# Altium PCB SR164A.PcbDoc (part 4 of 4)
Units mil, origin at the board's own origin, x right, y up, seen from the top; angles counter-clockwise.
Board outline 6100 x 4100 mil, 6 copper layers (Top Layer, Signal Layer 1, Signal Layer 2, Signal Layer 3, Signal Layer 4, Bottom Layer), stack 61.4 mil thick; 254 components, 116 nets, 656 pads, 2538 vias.
Unrouted connection lines stored in the file: 13.
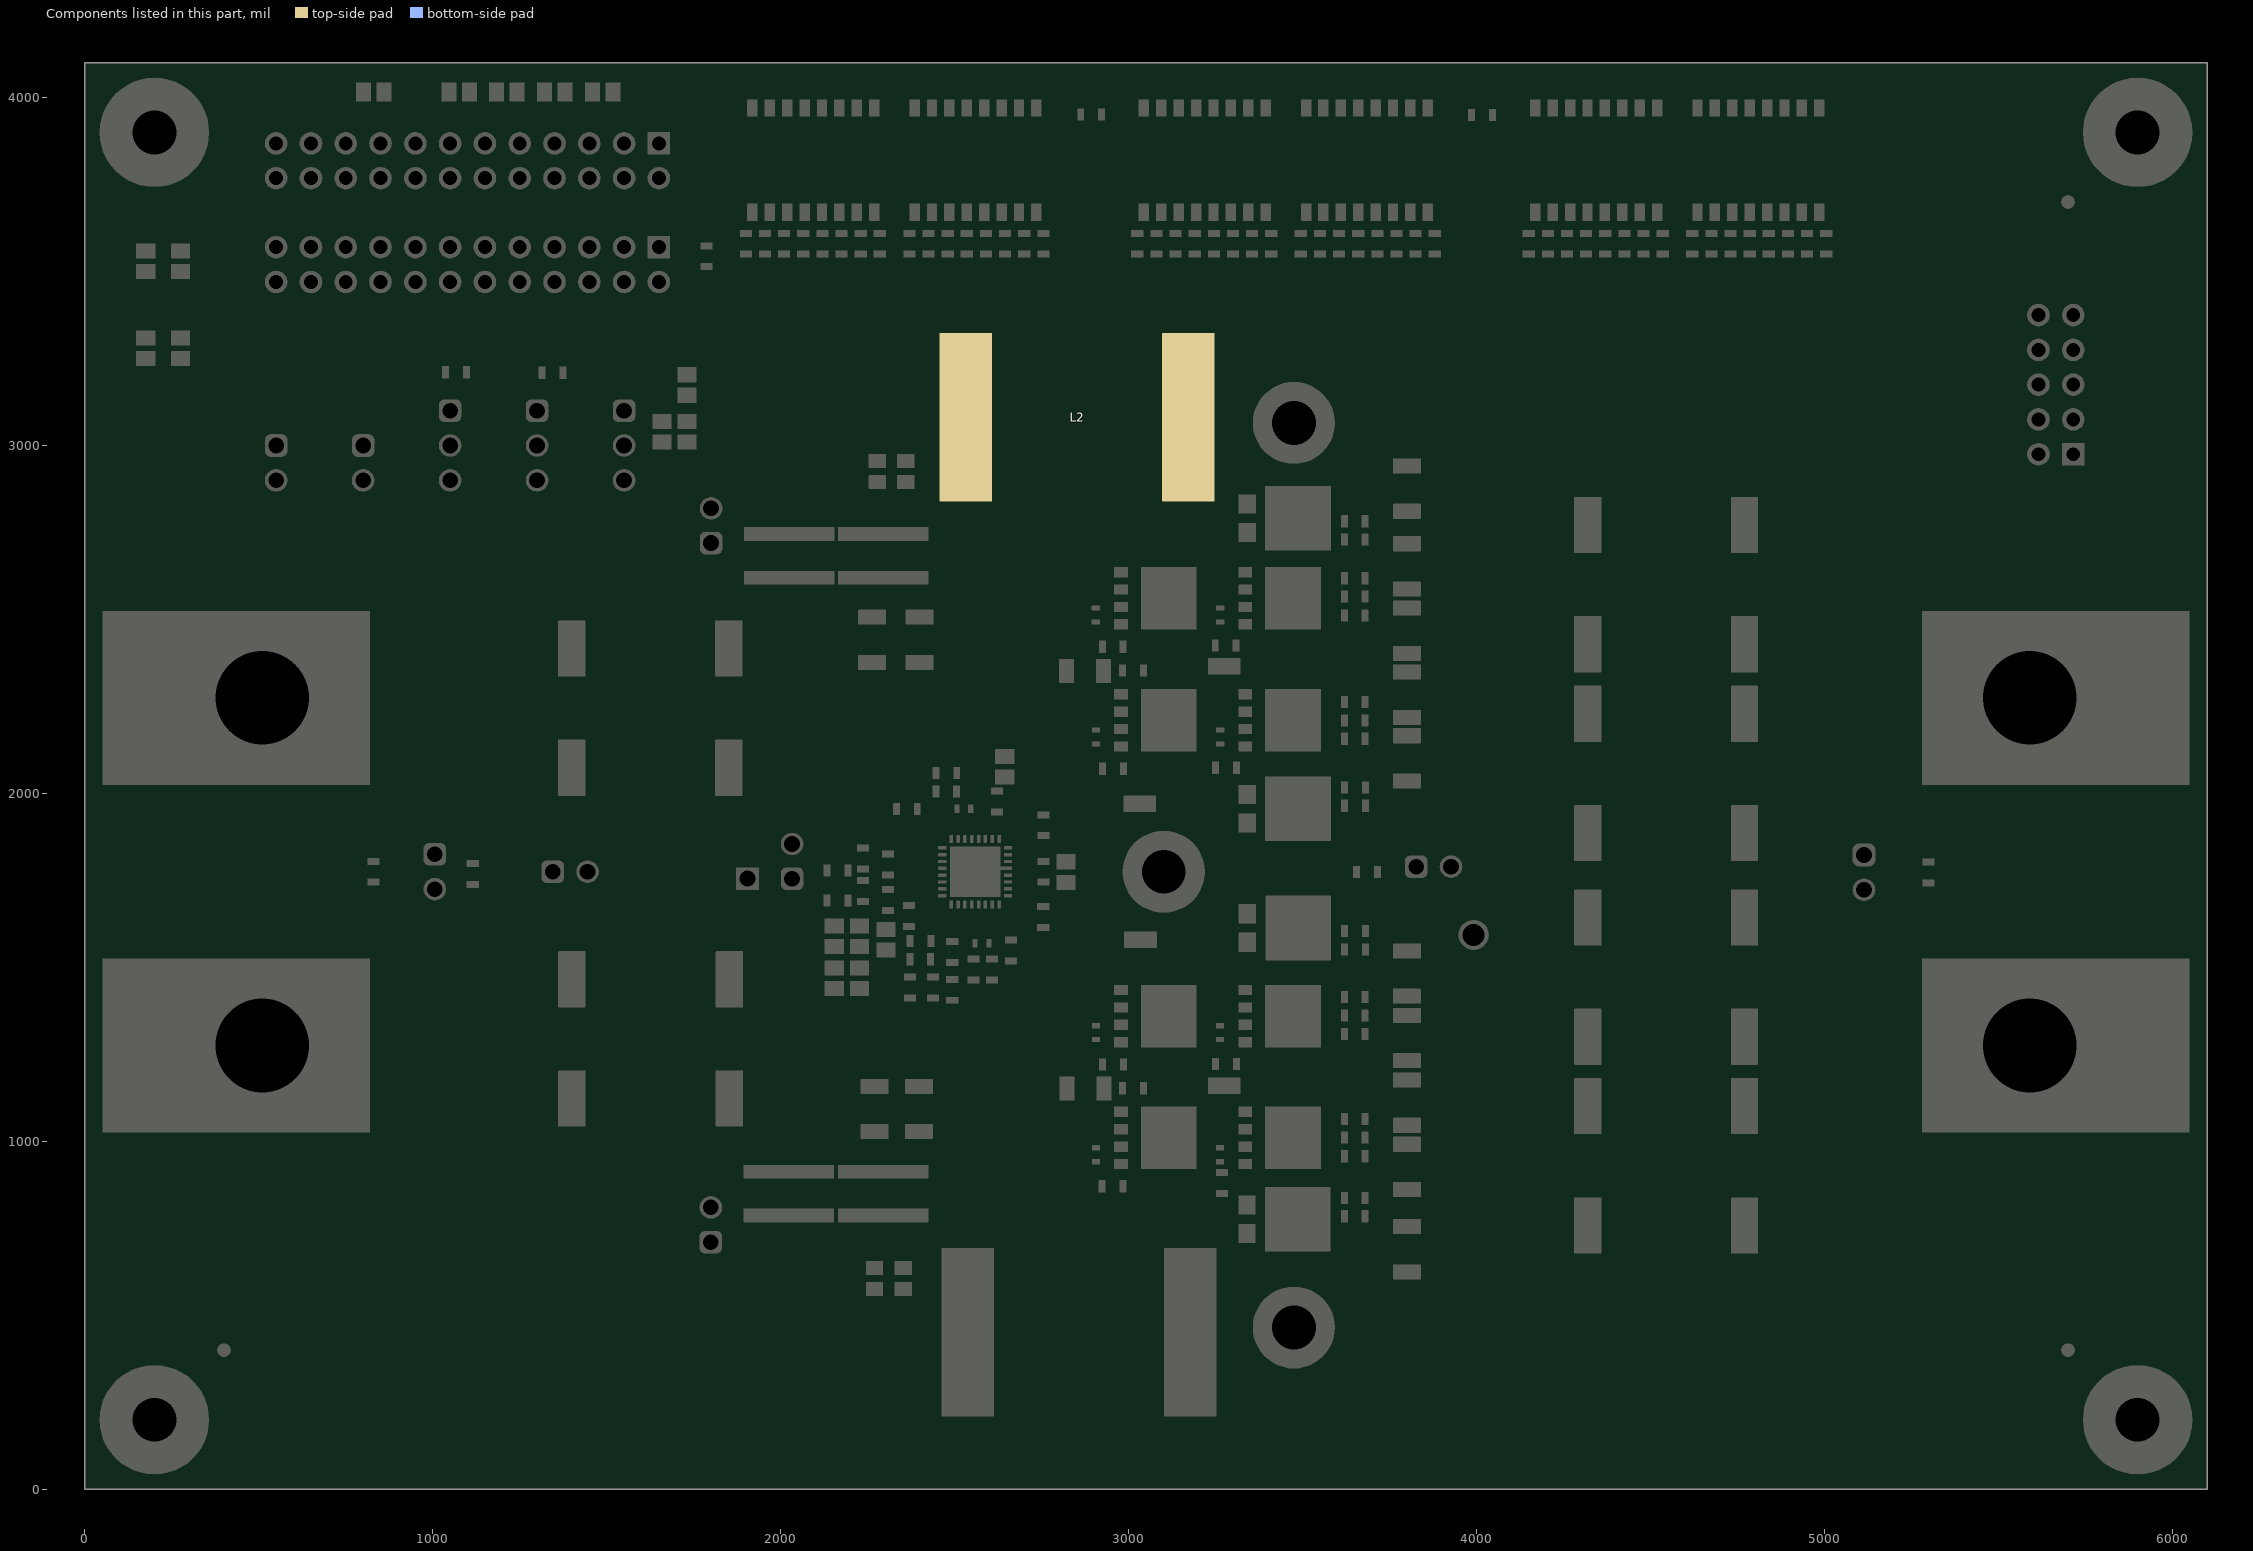
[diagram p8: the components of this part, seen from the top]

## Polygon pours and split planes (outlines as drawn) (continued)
NetC9_2 on Top Layer "TOP_LAYER_NETC9_2_P102" (solid, pour order 102): 2907.04,1185.68 2956.54,1185.68 2972.85,1169.37 2992.67,1169.37 2992.67,1134.37 2992.8,1134.24 2972.77,1134.24 2955.4,1116.87 2907.04,1116.87
NetQ4_4 on Top Layer "TOP_LAYER_NETQ4_4_P103" (solid, pour order 103): 3009.87,2066.09 3009.97,2150.41 2892.37,2150.41 2892.37,2115.7 2909.85,2098.21 2932.26,2098.21 2945.22,2085.25 2945.22,2054.78 2946.36,2053.64 2997.42,2053.64
SW1 on Top Layer "TOP_LAYER_SW1_P104" (solid, pour order 104): 3367.98,837.02 3367.98,1681.81 3363.28,1686.51 3247.06,1686.51 3031.4,1470.84 3031.34,695.36 2944.54,587.21 2944.54,352.87 3091.31,206.11 3261.43,206.11 3281.52,226.19 3281.52,647.87 3317.25,683.61 3367.98,683.61
AGND on Top Layer "TOP_LAYER_AGND_P106" (solid, pour order 106): 2152.22,2046.56 1982.71,1877.04 1982.71,1532.63 2141.03,1374.3 2603.02,1374.3 2682.95,1454.23 2682.95,1604.16 2645.51,1641.6 2645.51,1871.14 2671.11,1896.74 2671.11,2128.76 2632.74,2167.12 2272.78,2167.12
VIN on Top Layer "TOP_LAYER_VIN_P107" (solid, pour order 107): 1200,889.57 1228.21,861.36 2439.49,861.36 2439.49,1080.48 2422.85,1097.12 2474.44,1099.36 2003.62,1099.16 1879.57,1223.21 1228.21,1223.21 1200,1195
VIN on Top Layer "TOP_LAYER_VIN_P108" (solid, pour order 108): 1200.91,2341.25 1200.91,2645.91 1226.33,2671.33 2440.43,2671.33 2440.43,2444.04 2430.2,2433.8 1996.9,2433.35 1878.55,2315 1227.15,2315
SW2 on Top Layer "TOP_LAYER_SW2_P109" (solid, pour order 109): 3367.26,1887.34 3361.98,1882.07 3228.54,1882.07 3032.3,2078.31 3032.3,2839.02 2941.1,2950.76 2941.1,3180.42 3087.23,3326.55 3267.28,3326.55 3282.9,3310.93 3282.9,2935.35 3331.61,2888.05 3367.26,2888.05 3367.26,2692.26
VOUT on Top Layer "Bottom Layer-VOUT" (solid, pour order 110): 5137.79,1775.4 5090.84,1768.75 5066.11,1757.78 4970.51,1662.17 4920,1524.81 4920,1069.35 4817.07,937.93 4676.71,875 4133.9,875 3939.47,680.57 3390.02,680.57 3390.45,1740 3390.45,1833.39 3390,1833.39 3390,2888.05 3935.85,2888.04 3985.94,2837.96 4173.9,2650 4655,2650 6100,2650 6100,1775.4
VIN on Top Layer "TOP_LAYER_VIN_P130" (solid, remove dead copper, pour order 130): 925.07,2602.84 925.07,1932.49 899.97,1907.4 0,1907.4 0,2627.27 900.64,2627.27
GND on Top Layer "TOP_LAYER_AGND_P479" (solid, pour order 131): -26.23,4102.69 6073.77,4102.69 6073.77,2.69 -26.23,2.69
GND on Top Layer "TOP_LAYER_GND_P132" (solid, pour order 132): 3657.15,1290.81 3663.46,1284.5 3838.99,1284.5 3856.76,1302.26 3856.76,1403.77 3822.52,1438 3664.89,1438 3657.15,1430.26
GND on Bottom Layer "BOTTOM_LAYER_GND_P066" (solid, pour order 66): 2242.51,1189.21 2242.51,1129.51 2250.61,1121.41 2442.43,1121.41 2453.25,1132.23 2453.25,1182.71 2439.61,1196.35 2251.39,1196.35
GND on Bottom Layer "BOTTOM_LAYER_GND_P081" (solid, pour order 81): 2244.78,2344.73 2244.78,2404.42 2252.88,2412.53 2444.7,2412.53 2455.52,2401.71 2455.52,2351.23 2441.88,2337.59 2253.65,2337.59
VOUT on Bottom Layer "Bottom Layer-VOUT 4" (solid, pour order 91): 3404.38,2450.78 3409.84,2445.32 3559.84,2445.32 3565.87,2451.35 3565.87,2873.68 3558.85,2880.69 3411.12,2880.69 3404.38,2873.96
VOUT on Bottom Layer "Bottom Layer-VOUT 3" (solid, pour order 112): 3559.14,687.75 3565.87,696.12 3565.87,1120.19 3559.71,1126.34 3410.75,1126.34 3403.37,1117.16 3403.37,695 3410.62,687.75
VOUT on Bottom Layer "Bottom Layer-VOUT 2" (solid, pour order 116): 3403.37,1251.8 3409.84,1245.32 3559.84,1245.32 3567.38,1252.86 3567.38,1695.37 3559.4,1703.34 3411.67,1703.34 3403.37,1695.04
VOUT on Bottom Layer "Bottom Layer-VOUT 1" (solid, pour order 117): 3403.7,1874.1 3411.26,1866.54 3559,1866.54 3566.91,1874.45 3566.91,2319.15 3559.71,2326.34 3410.75,2326.34 3403.7,2317.57
SW1 on Bottom Layer "BOTTOM_LAYER_SW1_P118" (solid, pour order 118): 3043.45,1502.59 3192.41,1502.59 3198.45,1496.55 3198.45,1226.05 3191.34,1218.95 3043.5,1218.95 3036.4,1226.05 3036.4,1493.82
SW1 on Bottom Layer "BOTTOM_LAYER_SW1_P119" (solid, pour order 119): 3043.41,1152.27 3192.37,1152.27 3198.41,1146.23 3198.41,875.73 3191.31,868.62 3043.46,868.62 3036.36,875.72 3036.36,1143.5
SW2 on Bottom Layer "BOTTOM_LAYER_SW2_P120" (solid, pour order 120): 3043.41,2352.27 3192.37,2352.27 3198.41,2346.23 3198.41,2075.73 3191.31,2068.62 3043.46,2068.62 3036.36,2075.72 3036.36,2343.5
SW2 on Bottom Layer "BOTTOM_LAYER_SW2_P121" (solid, remove dead copper, pour order 121): 3043.45,2702.59 3192.41,2702.59 3198.45,2696.55 3198.45,2426.05 3191.34,2418.95 3043.5,2418.95 3036.4,2426.05 3036.4,2693.82
GND on Bottom Layer "BOTTOM_LAYER_GND_P122" (solid, remove dead copper, pour order 122): 2354.65,1121.07 2439.57,1121.07 2453.25,1134.76 2453.25,1182.71 2439.92,1196.04 2354.55,1196.04 2341.5,1182.99 2341.5,1134.23
GND on Bottom Layer "BOTTOM_LAYER_GND_P123" (solid, remove dead copper, pour order 123): 2251.96,1120.42 2310.84,1120.42 2324.52,1134.11 2324.52,1182.06 2311.19,1195.39 2251.1,1195.39 2243.78,1188.07 2243.78,1128.6
GND on Bottom Layer "BOTTOM_LAYER_GND_P124" (solid, remove dead copper, pour order 124): 2252.96,2412.87 2311.84,2412.87 2325.52,2399.18 2325.52,2351.23 2312.19,2337.9 2252.1,2337.9 2244.78,2345.22 2244.78,2404.69
GND on Bottom Layer "BOTTOM_LAYER_GND_P125" (solid, remove dead copper, pour order 125): 2356.92,2412.87 2441.84,2412.87 2455.52,2399.18 2455.52,2351.23 2442.19,2337.9 2356.82,2337.9 2343.77,2350.95 2343.77,2399.71
AGND on Bottom Layer "Bottom Layer-AGND" (solid, remove dead copper, pour order 126): 1395.05,1744.64 1942.19,1193.46 1942.19,952.68 2482.68,952.68 2678.04,1148.04 2678.04,1599.89 2650.26,1627.66 2618.51,1627.66 2588.57,1657.6 2588.57,1702.66 2632.27,1746.36 2632.27,1802.68 2586.47,1848.49 2586.47,1884.67 2678.04,1976.24 2680.66,3028.02 1942.19,3766.49 1942.19,3766.47 1633.17,4075.49 25.49,4075.49 25.49,2688.43 1650.94,2689.52 1744.89,2595.57 1942.19,2595.57 1942.19,2349.05 1395.05,1801.9
VOUT on Bottom Layer "BOTTOM_LAYER_VOUT_P127" (solid, remove dead copper, pour order 127): 5166.03,1940.68 5166.03,2611.03 5194.28,2639.28 6100,2639.28 6100,1916.26 5190.46,1916.26
GND on Bottom Layer "BOTTOM_LAYER_GND_P128" (solid, remove dead copper, pour order 128): 933.97,1609.32 933.97,938.97 905.72,910.72 0,910.72 0,1633.74 909.54,1633.74
VIN on Bottom Layer "Bottom Layer-VIN" (solid, remove dead copper, pour order 129): 1920,953.2 1732.69,953.2 1637.32,857.83 0,857.83 0,2668.29 1646.77,2668.29 1732.94,2582.12 1920,2582.12
VOUT on Bottom Layer "BOTTOM_LAYER_VOUT_P133" (solid, remove dead copper, pour order 133): 5166.03,1940.68 5166.03,2611.03 5191.13,2636.13 6100,2636.13 6100,1916.26 5190.46,1916.26
GND on Bottom Layer "TOP_LAYER_AGND_P479" (solid, pour order 134): 0,4100 6100,4100 6100,0 0,0
GND on Signal Layer 2 "Signal Layer 2-GND" (solid, remove dead copper, pour order 29): 2930.67,846.92 2962.66,878.91 2962.66,2635.34 2928,2670 2723.42,2670 2700,2646.58 2700,1969.04 2611.67,1880.71 2611.67,1850.05 2651.08,1810.64 2651.19,1735.54 2609.71,1694.06 2609.71,1663.05 2628.98,1643.78 2661.92,1643.78 2700,1605.7 2700,862.89 2715.97,846.92
AGND on Signal Layer 2 "TOP_LAYER_AGND_P479" (solid, pour order 51): -4,4109.92 6096,4109.92 6096,9.92 -4,9.92
GND on Signal Layer 3 "Signal Layer 3-GND" (solid, remove dead copper, pour order 70): 3373.81,1136.93 3373.81,1233.19 3373.81,2336.93 3373.81,2433.19 3373.81,2582.19 3253.94,2702.06 2757.49,2702.06 2700,2644.57 2700,1969.04 2611.67,1880.71 2611.67,1850.58 2651.39,1810.87 2651.5,1736.34 2609.71,1694.55 2609.71,1663.65 2629.92,1643.44 2660.82,1643.44 2700,1604.26 2700,863.29 2716.7,846.59 3299.06,846.59 3373.81,921.34
AGND on Signal Layer 3 "TOP_LAYER_AGND_P479" (solid, pour order 72): 0,4100 6100,4100 6100,0 0,0
GND on Signal Layer 4 "Signal Layer 4-GND" (solid, remove dead copper, pour order 47): 3373.81,921.34 3373.81,2582.19 3254,2702 2757.43,2702 2700,2644.57 2700,1967.8 2608.68,1876.48 2608.68,1855.65 2651.82,1812.51 2651.94,1736.78 2609.71,1694.55 2609.71,1663.65 2629.78,1643.57 2657.05,1643.57 2700,1600.62 2700,863.29 2733.29,830 3282.47,830
AGND on Signal Layer 4 "TOP_LAYER_AGND_P479" (solid, pour order 50): 0,4100 6100,4100 6100,0 0,0
no net on Top Solder "TOP_LAYER_NONET_P111" (solid): 2818.97,407.01 2771.97,407.01 2771.97,539.23 2818.97,539.23
no net on Top Solder "TOP_LAYER_NONET_P111" (solid): 2813.87,3125.65 2766.86,3125.65 2766.86,2993.43 2813.87,2993.43
no net on Top Solder "TOP_LAYER_NONET_P111" (solid): 2762.94,351.15 2623.6,351.15 2623.6,581.31 2762.94,581.31
no net on Top Solder "TOP_LAYER_NONET_P111" (solid): 2951.19,351.15 3090.53,351.15 3090.53,581.31 2951.19,581.31
no net on Top Solder "TOP_LAYER_NONET_P111" (solid): 2946.08,3181.5 3085.43,3181.5 3085.43,2951.34 2946.08,2951.34
L2 on Top Solder "TOP_LAYER_NONET_P111" (solid, pour order 111): 2757.84,3181.5 2618.49,3181.5 2618.49,2951.34 2757.84,2951.34
VOUT on Bottom Solder (solid, pour order 32): 3404.38,2450.78 3409.84,2445.32 3559.84,2445.32 3565.87,2451.35 3565.87,2873.68 3558.85,2880.69 3411.12,2880.69 3404.38,2873.96
VOUT on Bottom Solder (solid, pour order 33): 3559.14,687.75 3565.87,696.12 3565.87,1120.19 3559.71,1126.34 3410.75,1126.34 3403.37,1117.16 3403.37,695 3410.62,687.75
VOUT on Bottom Solder (solid, pour order 34): 3403.37,1251.8 3409.84,1245.32 3559.84,1245.32 3567.38,1252.86 3567.38,1695.37 3559.4,1703.34 3411.67,1703.34 3403.37,1695.04
VOUT on Bottom Solder (solid, pour order 35): 3403.7,1874.1 3411.26,1866.54 3559,1866.54 3566.91,1874.45 3566.91,2319.15 3559.71,2326.34 3410.75,2326.34 3403.7,2317.57
SW1 on Bottom Solder "BOTTOM_LAYER_SW1_P032" (solid, pour order 53): 3043.45,1502.59 3192.41,1502.59 3198.45,1496.55 3198.45,1226.05 3191.34,1218.95 3043.5,1218.95 3036.4,1226.05 3036.4,1493.82
SW1 on Bottom Solder "BOTTOM_LAYER_SW1_P033" (solid, pour order 113): 3043.41,1152.27 3192.37,1152.27 3198.41,1146.23 3198.41,875.73 3191.31,868.62 3043.46,868.62 3036.36,875.72 3036.36,1143.5
SW2 on Bottom Solder "BOTTOM_LAYER_SW2_P034" (solid, pour order 114): 3043.41,2352.27 3192.37,2352.27 3198.41,2346.23 3198.41,2075.73 3191.31,2068.62 3043.46,2068.62 3036.36,2075.72 3036.36,2343.5
SW2 on Bottom Solder "BOTTOM_LAYER_SW2_P035" (solid, pour order 115): 3043.45,2702.59 3192.41,2702.59 3198.45,2696.55 3198.45,2426.05 3191.34,2418.95 3043.5,2418.95 3036.4,2426.05 3036.4,2693.82
GND on Signal Layer 1 "TOP_LAYER_AGND_P479" (solid, pour order 25): 0,4100 6100,4100 6100,0 0,0

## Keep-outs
Keep-Out Layer:
  text ".Layer_Name" at 577,-858.49 h60

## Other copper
Top Layer:
  pour cut-out: 1756.46,808.93 ccw(c1800.03,808.93) 1800.03,765.36 ccw(c1800.03,808.93) 1843.59,808.93 ccw(c1800.03,808.93) 1800.03,852.5 ccw(c1800.03,808.93)
  pour cut-out: 961.56,1725.19 ccw(c1005.13,1725.19) 1005.13,1681.62 ccw(c1005.13,1725.19) 1048.7,1725.19 ccw(c1005.13,1725.19) 1005.13,1768.75 ccw(c1005.13,1725.19)
  pour cut-out: 961.56,1825.19 ccw(c1005.13,1825.19) 1005.13,1781.62 ccw(c1005.13,1825.19) 1048.7,1825.19 ccw(c1005.13,1825.19) 1005.13,1868.75 ccw(c1005.13,1825.19)
  pour cut-out: 5070.02,1722.8 ccw(c5113.59,1722.8) 5113.59,1679.24 ccw(c5113.59,1722.8) 5157.15,1722.8 ccw(c5113.59,1722.8) 5113.59,1766.37 ccw(c5113.59,1722.8)
  pour cut-out: 5069.2,1827.79 ccw(c5112.77,1827.79) 5112.77,1784.22 ccw(c5112.77,1827.79) 5156.33,1827.79 ccw(c5112.77,1827.79) 5112.77,1871.35 ccw(c5112.77,1827.79)
  pour cut-out: 2129,582.62 2189,582.62 2189,602.62 2129,602.62
  pour cut-out: 1832.67,857.11 1832.67,737.84 1891.43,737.84 1891.43,857.11
  pour cut-out: 1696.01,861.09 2243.09,861.09 2243.09,841.09 1696.01,841.09
  pour cut-out: 1087.36,1818.75 1087.36,1717.66 1142.87,1717.66 1142.87,1818.75
  pour cut-out: 2439.25,683.61 2439.25,597.62 2459.25,597.62 2459.25,683.61
  pour cut-out: 2439.29,800.37 2439.29,886.36 2459.29,886.36 2459.29,800.37
  pour cut-out: 2621.02,695.79 2821.93,539.22 2821.93,408.23 2608.27,194.57 2608.27,185.8 3097.8,185.8 3097.39,200.18 2947.54,350.03 2947.54,583.46 3030.87,685.72 3030.87,714.17 2621.99,714.17 2621.02,713.2
  pour cut-out: 3370.01,1253.19 3370.01,1110 3390.01,1110 3390.01,1253.19
  pour cut-out: 2424.33,1662.12 2424.33,1693.28 2459.78,1693.28 2459.78,1662.12
  pour cut-out: 2572.37,1520.37 2572.37,1544.86 2589.95,1544.86 2589.95,1520.37
  pour cut-out: 2635.22,1557.86 2635.22,1535.55 2622.52,1535.55 2622.52,1557.86
  pour cut-out: 2606.72,1557.86 2701.3,1557.86 2701.3,1652.44
  pour cut-out: 2628.4,1925.47 2628.4,1885.62 2620.37,1885.62 2620.37,1925.47
  pour cut-out: 2670.91,1917 2620.37,1917 2620.37,1925.02 2670.91,1925.02
  pour cut-out: 2702.73,1538.81 2702.73,1486.03 2690.03,1486.03 2690.03,1538.81
  pour cut-out: 1833.38,2672.86 1833.38,2792.12 1894.42,2792.12 1894.42,2672.86
  pour cut-out: 1702.72,2691.69 2246.08,2691.69 2246.08,2671.69 1702.72,2671.69
  pour cut-out: 2136.09,2949.01 2196.09,2949.01 2196.09,2929.01 2136.09,2929.01
  pour cut-out: 3369.38,2459.1 3369.38,2315.9 3389.38,2315.9 3389.38,2459.1
  pour cut-out: 2440.25,2818.48 2440.25,2935 2460.25,2935 2460.25,2818.48
  pour cut-out: 2616.89,2837.62 2815.5,2992.4 2815.5,3125.75 2613.24,3328.01 2613.24,3346.85 3092.69,3346.85 3092.29,3332.47 2942.44,3182.62 2942.44,2949.19 3032.2,2839.02 3032.2,2818.48 2616.89,2818.48
  pour cut-out: 2486.14,2073.27 2486.14,2113.8 2510.43,2113.8 2510.43,2073.27
  pour cut-out: 2670.91,1917.45 2670.91,2157.77 2693.36,2135.32 2694.01,1981.19 2694.18,1940.72
  pour cut-out: 2440.24,2651.38 2440.24,2737.36 2460.24,2737.36 2460.24,2651.38
  pour cut-out: 5070.02,1726.03 5070.02,1826.1 5279.6,1826.1 5279.6,1726.03
  pour cut-out: 5279.6,1680.07 5113.57,1680.07 5113.57,1759.03 5279.6,1759.03
  pour cut-out: 5280.36,1788.96 5113.46,1788.96 5113.46,1871.35 5280.36,1871.35
  text ".Layer_Name" at 577,-858.49 h60
Signal Layer 1:
  pour cut-out: 961.58,1725.11 ccw(c1005.15,1725.11) 1005.15,1681.54 ccw(c1005.15,1725.11) 1048.71,1725.11 ccw(c1005.15,1725.11) 1005.15,1768.67 ccw(c1005.15,1725.11)
  pour cut-out: 961.68,1825.1 ccw(c1005.25,1825.1) 1005.25,1781.54 ccw(c1005.25,1825.1) 1048.81,1825.1 ccw(c1005.25,1825.1) 1005.25,1868.67 ccw(c1005.25,1825.1)
  pour cut-out: 5070.16,1723.3 ccw(c5113.73,1723.3) 5113.73,1679.74 ccw(c5113.73,1723.3) 5157.29,1723.3 ccw(c5113.73,1723.3) 5113.73,1766.87 ccw(c5113.73,1723.3)
  pour cut-out: 5070.16,1823.3 ccw(c5113.73,1823.3) 5113.73,1779.74 ccw(c5113.73,1823.3) 5157.29,1823.3 ccw(c5113.73,1823.3) 5113.73,1866.87 ccw(c5113.73,1823.3)
  pour cut-out: 1087.36,1818.75 1087.36,1717.66 1142.87,1717.66 1142.87,1818.75
  pour cut-out: 2728.08,1823.11 2752.63,1823.11 2752.63,1725.88 2728.08,1725.88
  text ".Layer_Name" at 577,-858.49 h60
Signal Layer 2:
  pour cut-out: 963.27,1808.76 963.13,1808.62 963.13,1725 982.89,1725 982.89,1808.91
  pour cut-out: 3313.05,1793.06 2983.05,1793.06 2983.05,1754.9 2983.05,1554 3313.05,1757.81
  text ".Layer_Name" at 577,-858.49 h60
Signal Layer 3:
  pour cut-out: 2597.9,1853.37 2610.06,1865.53 2685.77,1789.82 2773.78,1789.82 2798.77,1764.82 2777.95,1744.01 2764.31,1757.65 2669.55,1757.65 2638.74,1788.46 2638.74,1799.11
  pour cut-out: 3015.19,2722.53 3220.19,2722.53 3220.19,2702.53 3015.19,2702.53
  text ".Layer_Name" at 577,-858.49 h60
Signal Layer 4:
  pour cut-out: 3011.14,2722.37 3216.14,2722.37 3216.14,2702.37 3011.14,2702.37
  text ".Layer_Name" at 577,-858.49 h60
Bottom Layer:
  pour cut-out: 961.68,1725.1 ccw(c1005.25,1725.1) 1005.25,1681.54 ccw(c1005.25,1725.1) 1048.81,1725.1 ccw(c1005.25,1725.1) 1005.25,1768.67 ccw(c1005.25,1725.1)
  pour cut-out: 961.68,1825.1 ccw(c1005.25,1825.1) 1005.25,1781.54 ccw(c1005.25,1825.1) 1048.81,1825.1 ccw(c1005.25,1825.1) 1005.25,1868.67 ccw(c1005.25,1825.1)
  pour cut-out: 5069.74,1724.01 ccw(c5113.3,1724.01) 5113.3,1680.44 ccw(c5113.3,1724.01) 5156.87,1724.01 ccw(c5113.3,1724.01) 5113.3,1767.57 ccw(c5113.3,1724.01)
  pour cut-out: 5069.86,1823.37 ccw(c5113.42,1823.37) 5113.42,1779.81 ccw(c5113.42,1823.37) 5156.99,1823.37 ccw(c5113.42,1823.37) 5113.42,1866.94 ccw(c5113.42,1823.37)
  pour cut-out: 1048.81,1850.63 1031.04,1868.4 978.03,1868.4 961.96,1852.34 961.96,1799.39 979.91,1781.45 1030.69,1781.45 1048.81,1799.58
  pour cut-out: 1092.35,1813.3 1092.35,1745.08 1137.21,1745.08 1137.21,1813.3
  text ".Layer_Name" at 577,-858.49 h60

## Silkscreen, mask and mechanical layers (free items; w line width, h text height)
Top Overlay:
  lines w10: 61.16,1818.64 60.45,1670.29 689.11,1670.29 ; 61.8,1820.53 690.46,1820.53 ; 689.77,1671.63 690.49,1819.98 ; 2032.92,1678.24 2032.92,1705.74 ; 2033.11,1902.92 2033.11,1930.42 ; 5336.25,1840.42 5335.54,1692.07 6044.2,1692.07 ; 5336.88,1842.31 6045.54,1842.31 ; 6044.86,1693.41 6045.57,1841.76
  text "CFG0" at 2270,4025 h30
  text "CFG1" at 3395,4025 h30
  text "CFG2" at 4520,4025 h30
  text "ATRK" at 1002.76,3941.7 h30
  text "PGOOD" at 1142.15,3941.7 h30
  text "SYNCIN" at 1633.86,3941.7 h30
  text "UVLO" at 1453.59,3940.93 h30
  text "EN2" at 1319.42,3939.61 h30
  text "MODE" at 782.51,3937.38 h30
  text "SECONDARY" at 458.24,3689.29 h30 r90
  text "SYNCOUT" at 1625.89,3653.92 h30
  text "PRIMARY" at 458.24,3426.66 h30 r90
  text "SDA" at 190.78,3367.85 h30 r90
  text "SCL" at 285.31,3366.32 h30 r90
  text "SDA" at 5394.39,3358.6 h30
  text "SCL" at 5866.66,3358.6 h30
  text "SS" at 1064.08,3350.64 h30 r90
  text "SDA" at 561.18,3320.65 h30 r90
  text "SCL" at 661.76,3320.65 h30 r90
  text "EN2" at 1365.82,3320.65 h30 r90
  text "MODE" at 862.92,3290.66 h30 r90
  text "COMP" at 963.5,3290.66 h30 r90
  text "ATRK" at 1164.66,3290.66 h30 r90
  text "SYNC" at 1663.39,3290.66 h30 r90
  text "PGOOD" at 1265.24,3260.67 h30 r90
  text "UVLO/EN" at 1466.4,3200.69 h30 r90
  text "PULL-UP" at 71.53,3195.84 h30 r90
  text "RESISTORS" at 125.77,3169.17 h30 r90
  text "ILIM/IMON" at 762.34,3155.7 h30 r90
  text "AGND" at 5377.5,3148.92 h30
  text "FPWM" at 868.47,3109.56 h30
  text "0.34*" at 1380.09,3105.39 h65
  text "VCC" at 1158.75,3079.11 h30
  text "VCC" at 908.22,3064.42 h30
  text "BIAS" at 1379.41,3064.42 h30
  text "PHASE 2" at 3966.79,3045 h40
  text "ATRK" at 375.97,2975.07 h30
  text "DLY" at 657.38,2975.07 h30
  text "MODE" at 878.23,2975.07 h30
  text "EN2" at 1158.75,2975.07 h30
  text "UVLO" at 1374.41,2975.07 h30
  text "AGND" at 880.02,2898.24 h30
  text "AGND" at 375.97,2883.13 h30
  text "AGND" at 627.39,2883.13 h30
  text "AGND" at 1128.76,2883.13 h30
  text "BIAS" at 1379.41,2883.13 h30
  text "DEM" at 907.77,2851.74 h30
  text "RS2" at 1657.36,2799.36 h30
  text "VIN" at 1657.36,2704.41 h30
  text "VOUT" at 5157.48,2244.09 h30 r90
  text "VIN" at 974.32,2225.73 h30 r90
  text "ATRK" at 1988.03,1987.51 h30
  text "EXTERNAL" at 1927.75,1946.24 h30
  text "BODE" at 3936.13,1905.2 h30
  text "VOUT_7" at 3602.36,1810.73 h30
  text "VIN" at 902.9,1805.17 h30 r90
  text "S+" at 943.91,1805 h30 r90
  text "VOUT" at 3988.27,1801.13 h30
  text "VOUT" at 5250.4,1791.56 h30 r90
  text "S+" at 5201.19,1791.12 h30 r90
  text "12.5A MAX" at 5354.7,1726.85 h80
  text "AGND" at 1720.46,1718.97 h30
  text "26A MAX" at 102.15,1704.11 h80
  text "S-" at 943.91,1700.98 h30 r90
  text "S-" at 5202.52,1679.24 h30 r90
  text "VIN" at 1278.21,1676.1 h30
  text "BIAS" at 1438.52,1676.1 h30
  text "GND" at 900.25,1671.39 h30 r90
  text "GND" at 5249.64,1647.04 h30 r90
  text "ATRK/DTRK" at 1753.31,1643.78 h30
  text "AGND" at 3935.84,1477.91 h30
  text "GND" at 5160.22,1244.09 h30 r90
  text "45V" at 2144.52,1229.68 h30 r90
  text "24V" at 2250.67,1228.29 h30 r90
  text "GND" at 964.17,1226.77 h30 r90
  text "ATRK" at 2197.17,1171.83 h30 r90
  text "VIN" at 1657.36,792.68 h30
  text "RS1" at 1657.36,694.18 h30
  text "'.PRJ_Title'" at 590.58,549.68 h60
  text ".PRJ_Number" at 588.58,465.67 h40
  text "PHASE 1" at 3966.79,445 h40
  text "REV. .PCB_Rev" at 588.58,383.86 h40
  text ".Layer_Name" at 577,-858.49 h60
Bottom Overlay:
  text ".Layer_Name" at 577,-858.49 h60
Top Paste:
  text ".Layer_Name" at 577,-858.49 h60
Bottom Paste:
  text ".Layer_Name" at 577,-858.49 h60
Top Solder:
  text ".Layer_Name" at 577,-858.49 h60
  text ".Layer_Name" at 577,-858.49 h60
Bottom Solder:
  text ".Layer_Name" at 577,-858.49 h60
Drill Guide:
  text ".Layer_Name" at 577,-858.49 h60
M1 Board Outline:
  the board outline again, w10
  text ".Layer_Name" at 577,-858.49 h60
M2 Board Dimensions:
  rectangle: 125,-400 500,-275
  rectangle: 0,-275 125,-150
  lines w7: 0,-275 1000,-275 ; 125,-400 125,-150 ; 250,-400 250,-150 ; 500,-400 500,-150 ; 750,-400 750,-150 ; 0,-400 1000,-400 1000,-150 0,-150 0,-400
  text ".Layer_Name" at 577,-858.49 h60
M3 3D STEP Top:
  text ".Layer_Name" at 577,-858.49 h60
M4 3D STEP Bottom:
  text ".Layer_Name" at 577,-858.49 h60
Top M5 Assembly Top/M6 Assembly Bottom:
  lines w10: -292,-930.17 6308,-930.17 ; -292,-726.83 6310,-726.83 ; -292,-523.5 -292,-1133.5 3713,-1133.5 6310,-1133.5 6310,-523.5 -291.5,-523.5 -291.5,-1133.5 1284,-1133.5 ; 2173,-1133.5 2173,-523.5 ; 3440,-726.83 3440,-523.5 ; 4280,-726.83 4280,-523.5 ; 4902,-1140 4902,-937.17
  text "COMPONENTS MARKED 'DNP' SHOULD NOT BE POPULATED." at 1153.5,-318.5 h60
  text "ASSEMBLY VARIANT:" at 1153,-434 h60
  text ".VariantName" at 2189,-434 h60
  text "PCB VIEWED FROM TOP SIDE" at -228.5,-655.67 h60
  text "BOARD #:" at 2248,-655.67 h60
  text ".PRJ_Number" at 2793.5,-655.67 h60
  text "REV:" at 3638,-655.67 h60
  text ".PCB_Rev" at 3929.5,-655.67 h60
  text "SVN REV:" at 4476,-655.67 h60
  text ".VersionControl_RevNumber" at 4982,-655.67 h60
  text "TID #:" at 2248,-859 h60
  text ".TID" at 2793.5,-859 h60
  text "PLOT NAME =" at -228.5,-1064.34 h60
  text ".plot_File_Name" at 577,-1064.34 h60
  text "GENERATED    :" at 2250,-1064.34 h60
  text ".Print_Date" at 3119.5,-1064.34 h60
  text ".Print_Time" at 3848.5,-1064.34 h60
  text "TEXAS INSTRUMENTS" at 5113,-1064.34 h60
Bottom M5 Assembly Top/M6 Assembly Bottom:
  lines w10: -292.5,-727.33 6309.5,-727.33 ; -290.5,-930.67 6309.5,-930.67 ; 1115.5,-1140.5 1115.5,-937.67 ; 1737.5,-727.33 1737.5,-524 ; 2577.5,-727.33 2577.5,-524 ; 3844.5,-1134 3844.5,-524 ; 4733.5,-1134 6309,-1134 6309,-524 -292.5,-524 -292.5,-1134 2304.5,-1134 6309.5,-1134 6309.5,-524
  text "COMPONENTS MARKED 'DNP' SHOULD NOT BE POPULATED." at 6102,-318 h60
  text ".VariantName" at 5058,-434 h60
  text "ASSEMBLY VARIANT:" at 6097,-434 h60
  text ".VersionControl_RevNumber" at 1035.5,-656.17 h60
  text "SVN REV:" at 1541.5,-656.17 h60
  text ".PCB_Rev" at 2088,-656.17 h60
  text "REV:" at 2379.5,-656.17 h60
  text ".PRJ_Number" at 3224,-656.17 h60
  text "BOARD #:" at 3769.5,-656.17 h60
  text "PCB VIEWED FROM BOTTOM SIDE" at 6246,-656.17 h60
  text ".TID" at 3224,-859.5 h60
  text "TID #:" at 3769.5,-859.5 h60
  text "TEXAS INSTRUMENTS" at 904.5,-1064.84 h60
  text ".Print_Time" at 2169,-1064.84 h60
  text ".Print_Date" at 2898,-1064.84 h60
  text "GENERATED    :" at 3767.5,-1064.84 h60
  text ".plot_File_Name" at 5440.5,-1064.84 h60
  text "PLOT NAME =" at 6246,-1064.84 h60
M9 Title Sheet:
  drawing of 57 lines, arcs and shapes, not listed
  text "1" at 739.84,8036.5 h70
  text "2" at 3235.5,8036.5 h70
  text "3" at 5724.84,8036.5 h70
  text "4" at 8231.51,8036.5 h70
  text "5" at 10730.5,8036.5 h70
  text "6" at 13235.5,8036.5 h70
  text "A" at -416.5,6893.5 h70
  text "A" at 14383.5,6893.5 h70
  text "B" at -416.5,4513.5 h70
  text "B" at 14383.5,4513.5 h70
  text "C" at -416.5,2138.5 h70
  text "C" at 14383.5,2138.5 h70
  text "PROJECT TITLE:" at 11343.5,277.5 h45
  text ".PRJ_Title" at 11393.5,144.17 h70
  text "DESIGNED FOR:" at 11343.5,-23.5 h45
  text ".PRJ_Customer" at 11393.5,-163.5 h70
  text "D" at -416.5,-231.5 h70
  text "D" at 14383.5,-231.5 h70
  text "FILE NAME:" at 11343.5,-323.5 h45
  text ".PCB_File_Name_No_Path" at 11393.5,-443.5 h70
  text "Texas Instruments (TI) and/or its licensors do not warrant the accuracy or completeness of this specification" at 6374,-605.34 h45
  text "ENGINEER:" at 11343.5,-613.5 h45
  text "LAYOUT BY:" at 12848.5,-613.5 h45
  text "or any information contained therein. TI and/or its licensors do not warrant that this design will meet" at 6329.01,-718 h45
  text ".PRJ_Engineer" at 11393.5,-768.49 h70
  text ".PCB_Layout" at 12899,-768.49 h70
  text "the specifications, will be suitable for your application or fit for any particular purpose, or will operate in" at 6329.01,-830.67 h45
  text ".Layer_Name" at 577,-858.49 h60
  text "ALTIUM DESIGNER VERSION:" at 12848.5,-923.5 h45
  text "an implementation. TI and/or its licensors do not warrant that the design is production worthy. You should" at 6329.01,-943.33 h45
  text "completely validate and test your design implementation to confirm the system functionality for your application." at 6374,-1056 h45
  text ".print_Scale" at 11393.5,-1056.83 h70
  text ".Application_BuildNumber" at 12899,-1056.83 h70
  text "1" at 739.84,-1263.5 h70
  text "2" at 3235.5,-1263.5 h70
  text "3" at 5724.84,-1263.5 h70
  text "4" at 8231.51,-1263.5 h70
  text "5" at 10730.5,-1263.5 h70
  text "6" at 13235.5,-1263.5 h70
M10 Fab Notes:
  drawing of 189 lines, arcs and shapes, not listed
  text "DESIGN INFORMATION" at 12381.98,6356.17 h60
  text "MIN. COPPER WIDTH:" at 11737.42,6224.05 h60
  text "6" at 12833.66,6224.05 h60
  text "MIL" at 12988.42,6224.05 h60
  text "6" at 12834.6,6102.36 h60
  text "MIN. CLEARANCE:" at 11737.42,6099.92 h60
  text "MIL" at 12988.42,6099.92 h60
  text "19.685" at 12631.3,5977.79 h60
  text "MIN. VIA PAD SIZE:" at 11737.42,5975.8 h60
  text "MIL" at 12988.42,5975.8 h60
  text "0.05mm (2MIL)" at 12432.42,5845.9 h60
  text "MINIMUM ANNULAR RING" at 11408.19,5837.67 h60
  text "EXTERNAL" at 13140.42,5837.67 h60
  text "PER" at 11608.19,5727.55 h60
  text "IPC-D-275 CLASS 2 LEVEL C" at 11828.19,5727.54 h60
  text "MIL, HOLES" at 13316.42,5627.07 h60
  text "+/-" at 12923.96,5618.48 h60
  text "+/-" at 13777.96,5618.48 h60
  text "REGISTRATION TOLERANCES:" at 11408.19,5617.42 h60
  text "METAL" at 12607.96,5617.42 h60
  text "5" at 13184.16,5617.42 h60
  text "3" at 14017.16,5617.42 h60
  text "MIL" at 14133.42,5617.42 h60
  text "HOLE SIZE TOLERANCE (UNLESS OTHERWISE SPECIFIED):" at 11408.19,5519.1 h60
  text "+/-" at 13777.96,5516.23 h60
  text "3" at 14017.16,5515.17 h60
  text "MIL" at 14133.42,5515.17 h60
  text "MATERIAL:" at 11333.42,5377.52 h60
  text "FR-4 High Tg" at 12319.86,5249 h60
  text "X" at 12175.42,5241.01 h60
  text "FR-4" at 11754.42,5236.49 h60
  text "OTHER" at 13242.42,5236.49 h60
  text "62 MIL (1.6mm) +/-10%" at 12074.52,5093.46 h60
  text "X" at 11954.42,5091.01 h60
  text "THICKNESS:" at 11408.19,5085.24 h60
  text "OTHER" at 13359.42,5085.24 h60
  text "TOLERANCE:" at 11408.19,4946.92 h60
  text "X" at 12256.42,4946.92 h60
  text "ANSI IPC-6012 TYPE 3 CLASS 2" at 12434.43,4946.92 h60
  text "OTHER +/-" at 12434.42,4802.73 h60
  text "BOW & TWIST:" at 11408.19,4657.54 h60
  text "X" at 12256.42,4657.54 h60
  text "ANSI IPC-6012 TYPE 3 CLASS 2" at 12434.43,4657.54 h60
  text "OTHER +/-" at 12434.42,4510.85 h60
  text "DRILLING:" at 11333.42,4380.23 h60
  text "NC_DRILL FILES" at 13094.42,4275.04 h60
  text "REFERENCE:" at 11408.19,4271.1 h60
  text "X" at 12065.42,4271.01 h60
  text "AS SHOWN" at 12243.42,4271.1 h60
  text "X" at 12966.42,4271.1 h60
  text "OTHER" at 13392.42,4128.85 h60
  text "PTH COPPER THICKNESS:" at 11407.86,4125.32 h60
  text "X" at 12547.1,4125.32 h60
  text "20-30 um" at 12675.09,4125.32 h60
  text "BOARD FINISH:" at 11333.42,3977.73 h60
  text "SILKSCREEN:" at 11488.64,3867.6 h60
  text "X" at 12446.42,3867.6 h60
  text "TOP" at 12563.42,3867.6 h60
  text "BOTTOM" at 13074.42,3867.6 h60
  text "SILKSCREEN COLOR:" at 11488.64,3712.41 h60
  text "X" at 12445.42,3712.41 h60
  text "WHITE" at 12563.42,3712.41 h60
  text "OTHER" at 13074.42,3712.41 h60
  text "X" at 12576.42,3568.96 h60
  text "GREEN" at 12694.42,3568.96 h60
  text "OTHER" at 13312.42,3568.96 h60
  text "SOLDER RESIST COLOR:" at 11488.64,3562.1 h60
  text "MATTE" at 12694.42,3414.71 h60
  text "SEMI-GLOSS" at 13311.96,3414.07 h60
  text "IMMERSION GOLD (ENIG)" at 12394.42,3241.94 h60
  text "ENEPIG" at 13731.96,3234.72 h60
  text "SURFACE FINISH:" at 11333.42,3233.72 h60
  text "X" at 12216.42,3233.72 h60
  text "IMM. TIN/SILVER OR EQUIV" at 11662.96,3096.4 h60
  text "OTHER" at 13094.42,3092.47 h60
  text "ARRAY/PANEL:" at 11333.42,2937.09 h60
  text "CUT AND TRIM PER M1 BOARD OUTLINE" at 12394.42,2928.87 h60
  text "N.C. ROUTE" at 12394.42,2792.9 h60
  text "X" at 13082.42,2792.9 h60
  text "V. SCORE" at 13260.42,2792.9 h60
  text "CERTIFICATION:" at 11333.42,2663.77 h60
  text "MATERIALS AND WORKMANSHIP FOR ALL PCBS" at 12058.42,2663.77 h60
  text "TO MEET OR EXCEED THE REQUIREMENTS OF:" at 12058.42,2569.71 h60
  text "X" at 11695.93,2441.08 h60
  text "ANSI IPC-A-600F CLASS ->" at 11823.92,2441.08 h60
  text "X" at 13471.93,2441.08 h60
  text "2" at 13581.92,2441.08 h60
  text "1" at 13266.92,2439.58 h60
  text "3" at 13935.92,2439.58 h60
  text "X" at 12507.93,2293.39 h60
  text "RoHS" at 12635.92,2293.39 h60
  text "OTHER" at 13280.32,2293.39 h60
  text "PER ORDER" at 13677.38,2293.39 h60
  text "ALL BOARDS MUST MEET OR EXCEED UL94-V0 REQUIREMENTS." at 11360.96,2139.57 h60
  text "PCB MUST BEAR THE UL94V-0 UL REGISTERED MATERIAL ID NUMBER" at 11360.96,2023.5 h60
  text "ADDITIONAL REQUIREMENTS:" at 11333.42,1854.08 h60
  text "MICROSECTION:" at 11408.19,1746.95 h60
  text "YES" at 12313.92,1746.95 h60
  text "REQUIRED" at 13175.42,1602.62 h60
  text "BARE BOARD ELEC. TEST:" at 11408.19,1599.76 h60
  text "NONE" at 12713.92,1599.76 h60
  text "X" at 13057.42,1599.76 h60
  text "PER ORDER" at 13767.42,1599.76 h60
  text "X" at 11464.62,1446.94 h60
  text "VIAS REQUIRE NON-CONDUCTIVE FILL AND PLANARIZE" at 11547.83,1381 h59
  text "XX MIL VIAS REQUIRE CONDUCTIVE FILL AND PLANARIZE" at 11584.34,1290.84 h60
  text "OUTER XX MIL TRACES REQUIRE 50 OHM SINGLE-ENDED IMPEDANCE" at 11583.35,1127.46 h58
  text "LAYER 2 & 3 (INNER LAYERS) XX MIL WIDE, XX MIL SPACE / TRACES REQUIRE 100 OHM DIFFERENTIAL IMPEDANCE" at 11575.35,891.74 h60
  text "X" at 1023.31,452.84 h60
  text "X" at 1077.36,279.4 h60
  text ".Layer_Name" at 577,-858.49 h60
M11 Gerber Information:
  lines w10: -292,-930.17 6308,-930.17 ; -292,-726.83 6310,-726.83 ; -292,-523.5 -292,-1133.5 3713,-1133.5 6310,-1133.5 6310,-523.5 -291.5,-523.5 -291.5,-1133.5 1284,-1133.5 ; 2173,-1133.5 2173,-523.5 ; 3440,-726.83 3440,-523.5 ; 4280,-726.83 4280,-523.5 ; 4902,-1140 4902,-937.17
  text "ALL ARTWORK VIEWED FROM TOP SIDE" at -228.5,-655.67 h60
  text "BOARD #:" at 2248,-655.67 h60
  text ".PRJ_Number" at 2793.5,-655.67 h60
  text "REV:" at 3638,-655.67 h60
  text ".PCB_Rev" at 3929.5,-655.67 h60
  text "SVN REV:" at 4476,-655.67 h60
  text ".VersionControl_RevNumber" at 4982,-655.67 h60
  text "LAYER NAME =" at -228.5,-858.49 h60
  text "TID #:" at 2248,-859 h60
  text ".TID" at 2793.5,-859 h60
  text "PLOT NAME =" at -228.5,-1064.34 h60
  text ".plot_File_Name" at 577,-1064.34 h60
  text "GENERATED    :" at 2250,-1064.34 h60
  text ".Print_Date" at 3119.5,-1064.34 h60
  text ".Print_Time" at 3848.5,-1064.34 h60
  text "TEXAS INSTRUMENTS" at 5113,-1064.34 h60
M12 Stackup:
  drawing of 373 lines, arcs and shapes, not listed
  text "Layer" at 6795.61,7854.8 h60
  text "Name" at 7205.52,7854.8 h60
  text "Material" at 8145.26,7854.8 h60
  text "Thickness" at 9005.03,7854.8 h60
  text "Constant" at 9654.87,7854.8 h60
  text "Board Layer Stack" at 10224.73,7854.8 h60
  text "Top Overlay" at 7205.52,7734.8 h60
  text "Top Solder" at 7205.52,7614.8 h60
  text "Solder Resist" at 8145.26,7614.8 h60
  text "0.50mil" at 9005.03,7614.8 h60
  text "3.5" at 9654.87,7614.8 h60
  text "1" at 6795.61,7494.8 h60
  text "Top Layer" at 7205.52,7494.8 h60
  text "2.80mil" at 9005.03,7494.8 h60
  text "Dielectric 1" at 7205.52,7374.8 h60
  text "FR-4 High Tg" at 8145.26,7374.8 h60
  text "7.00mil" at 9005.03,7374.8 h60
  text "4.2" at 9654.87,7374.8 h60
  text "2" at 6795.61,7254.8 h60
  text "Signal Layer 1" at 7205.52,7254.8 h60
  text "1.40mil" at 9005.03,7254.8 h60
  text "Dielectric 2" at 7205.52,7134.8 h60
  text "FR-4 High Tg" at 8145.26,7134.8 h60
  text "14.00mil" at 9005.03,7134.8 h60
  text "4.2" at 9654.87,7134.8 h60
  text "3" at 6795.61,7014.8 h60
  text "Signal Layer 2" at 7205.52,7014.8 h60
  text "1.40mil" at 9005.03,7014.8 h60
  text "Dielectric 4" at 7205.52,6894.8 h60
  text "FR-4 High Tg" at 8145.26,6894.8 h60
  text "8.20mil" at 9005.03,6894.8 h60
  text "4.2" at 9654.87,6894.8 h60
  text "4" at 6795.61,6774.8 h60
  text "Signal Layer 3" at 7205.52,6774.8 h60
  text "1.40mil" at 9005.03,6774.8 h60
  text "Dielectric 5" at 7205.52,6654.8 h60
  text "FR-4 High Tg" at 8145.26,6654.8 h60
  text "14.00mil" at 9005.03,6654.8 h60
  text "4.2" at 9654.87,6654.8 h60
  text "5" at 6795.61,6534.8 h60
  text "Signal Layer 4" at 7205.52,6534.8 h60
  text "1.40mil" at 9005.03,6534.8 h60
  text "Dielectric 3" at 7205.52,6414.8 h60
  text "FR-4 High Tg" at 8145.26,6414.8 h60
  text "7.00mil" at 9005.03,6414.8 h60
  text "4.2" at 9654.87,6414.8 h60
  text "6" at 6795.61,6294.8 h60
  text "Bottom Layer" at 7205.52,6294.8 h60
  text "2.80mil" at 9005.03,6294.8 h60
  text "Bottom Solder" at 7205.52,6174.8 h60
  text "Solder Resist" at 8145.26,6174.8 h60
  text "0.50mil" at 9005.03,6174.8 h60
  text "3.5" at 9654.87,6174.8 h60
  text "Total board thickness:" at 6795.61,6054.8 h60
  text "62.40mil" at 9005.03,6054.8 h60
  text ".Layer_Name" at 577,-858.49 h60
M13 Component Bodies Top:
  text ".Layer_Name" at 577,-858.49 h60
M14 Component Bodies Bottom:
  text ".Layer_Name" at 577,-858.49 h60
M15 Courtyards Top:
  text ".Layer_Name" at 577,-858.49 h60
M16 Courtyards Bottom:
  text ".Layer_Name" at 577,-858.49 h60
Drill Drawing:
  circle w10: c6833.59,5381.38 r16.58
  circle w10: c6833.59,5381.38 r27.63
  circle w10: c6833.59,4884.1 r27.63
  lines w10: 6805.96,4607.84 6833.59,4621.65 6861.21,4607.84 6847.4,4635.46 6861.21,4663.09 6833.59,4649.28 6805.96,4663.09 6819.77,4635.46 6805.96,4607.84 ; 6805.96,4787.41 6861.21,4787.41 6833.59,4732.16 6805.96,4787.41 ; 6805.96,4980.8 6861.21,4980.8 6861.21,5036.05 6805.96,5036.05 6805.96,4980.8 ; 6805.96,5118.93 6819.77,5118.93 6833.59,5105.12 6847.4,5118.93 6861.21,5118.93 6847.4,5132.74 6861.21,5146.56 6847.4,5146.56 6833.59,5160.37 6819.77,5146.56 6805.96,5146.56 6819.77,5132.74 6805.96,5118.93 ; 6805.96,5229.44 6805.96,5243.25 6819.77,5257.06 6805.96,5270.88 6805.96,5284.69 6819.77,5284.69 6833.59,5270.88 6847.4,5284.69 6861.21,5284.69 6861.21,5270.88 6847.4,5257.06 6861.21,5243.25 6861.21,5229.44 6847.4,5229.44 6833.59,5243.25 6819.77,5229.44 6805.96,5229.44 ; 6805.96,5478.08 6861.21,5478.08 6861.21,5533.33 6805.96,5533.33 6805.96,5478.08 ; 6805.96,5616.21 6819.77,5616.21 6819.77,5602.4 6847.4,5602.4 6847.4,5616.21 6861.21,5616.21 6861.21,5643.84 6847.4,5643.84 6847.4,5657.65 6819.77,5657.65 6819.77,5643.84 6805.96,5643.84 6805.96,5616.21 ; 6817.01,4991.85 6850.16,4991.85 6850.16,5025 6817.01,5025 6817.01,4991.85
  lines w12: 6755.87,4570.54 9987.52,4570.54 ; 6755.87,5689.42 9987.52,5689.42 ; 7093.73,4446.22 7093.73,5813.74 ; 7425.9,4446.22 7425.9,5813.74 ; 8062.46,4446.22 8062.46,5813.74 ; 8321.6,4446.22 8321.6,5813.74 ; 8696.76,4446.22 8696.76,5813.74 ; 9421.09,4446.22 9421.09,5813.74 ; 6755.87,4446.22 9987.52,4446.22 9987.52,5813.74 6755.87,5813.74 6755.87,4446.22
  text "Symbol" at 6830.46,5726.72 h72
  text "Quantity" at 7131.03,5726.72 h72
  text "Finished Hole Size" at 7463.19,5726.72 h72
  text "Plated" at 8099.76,5726.72 h72
  text "Hole Type" at 8358.9,5726.72 h72
  text "Drill Layer Pair" at 8734.05,5726.72 h72
  text "Hole Tolerance" at 9458.39,5726.72 h72
  text "12" at 7131.03,5602.4 h60
  text "7.87mil (0.200mm)" at 7463.19,5602.4 h60
  text "PTH" at 8099.76,5602.4 h60
  text "Round" at 8358.9,5602.4 h60
  text "Top Layer - Bottom Layer" at 8734.05,5602.4 h60
  text "2290" at 7131.03,5478.08 h60
  text "8.00mil (0.203mm)" at 7463.19,5478.08 h60
  text "PTH" at 8099.76,5478.08 h60
  text "Round" at 8358.9,5478.08 h60
  text "Top Layer - Bottom Layer" at 8734.05,5478.08 h60
  text "232" at 7131.03,5353.76 h60
  text "16.00mil (0.406mm)" at 7463.19,5353.76 h60
  text "PTH" at 8099.76,5353.76 h60
  text "Round" at 8358.9,5353.76 h60
  text "Top Layer - Bottom Layer" at 8734.05,5353.76 h60
  text "58" at 7131.03,5229.44 h60
  text "40.00mil (1.016mm)" at 7463.19,5229.44 h60
  text "PTH" at 8099.76,5229.44 h60
  text "Round" at 8358.9,5229.44 h60
  text "Top Layer - Bottom Layer" at 8734.05,5229.44 h60
  text "28" at 7131.03,5105.12 h60
  text "45.28mil (1.150mm)" at 7463.19,5105.12 h60
  text "PTH" at 8099.76,5105.12 h60
  text "Round" at 8358.9,5105.12 h60
  text "Top Layer - Bottom Layer" at 8734.05,5105.12 h60
  text "1" at 7131.03,4980.8 h60
  text "63.00mil (1.600mm)" at 7463.19,4980.8 h60
  text "PTH" at 8099.76,4980.8 h60
  text "Round" at 8358.9,4980.8 h60
  text "Top Layer - Bottom Layer" at 8734.05,4980.8 h60
  text "4" at 7131.03,4856.48 h60
  text "118.11mil (3.000mm)" at 7463.19,4856.48 h60
  text "PTH" at 8099.76,4856.48 h60
  text "Round" at 8358.9,4856.48 h60
  text "Top Layer - Bottom Layer" at 8734.05,4856.48 h60
  text "7" at 7131.03,4732.16 h60
  text "125.98mil (3.200mm)" at 7463.19,4732.16 h60
  text "PTH" at 8099.76,4732.16 h60
  text "Round" at 8358.9,4732.16 h60
  text "Top Layer - Bottom Layer" at 8734.05,4732.16 h60
  text "4" at 7131.03,4607.84 h60
  text "270.00mil (6.858mm)" at 7463.19,4607.84 h60
  text "PTH" at 8099.76,4607.84 h60
  text "Round" at 8358.9,4607.84 h60
  text "Top Layer - Bottom Layer" at 8734.05,4607.84 h60
  text "2636 Total" at 7131.03,4483.52 h60
  text ".Layer_Name" at 577,-858.49 h60
M17 Embedded Cavity:
  text ".Layer_Name" at 577,-858.49 h60
M18 Embedded Assembly:
  text ".Layer_Name" at 577,-858.49 h60
M19 Embedded Keepout:
  text ".Layer_Name" at 577,-858.49 h60

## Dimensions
0,0 to 6100,0 on M2 Board Dimensions
0,-400 to 1000,-400 on M2 Board Dimensions
0,0 to 0,4100 on M2 Board Dimensions
0,0 to 6100,0 on M2 Board Dimensions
